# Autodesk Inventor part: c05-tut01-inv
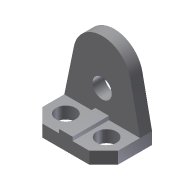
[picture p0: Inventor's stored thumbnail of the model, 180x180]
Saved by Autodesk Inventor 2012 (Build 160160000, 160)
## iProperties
Created: 2010-02
Part Number: c05-tut01-inv
Document SubType Name: Modeling
Designer: CADSoft
Density: 1 g/cm^3
Material: Default
Author: CADSoft
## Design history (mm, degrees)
sketch "Sketch1"
  geometry: L1 (-200, 0)-(0, 0); L2 (0, 0)-(0, -90); L3 (-38, -128)-(-162, -128); L4 (-200, -90)-(-200, 0); L5 (-200, -90)-(-162, -128); L6 (0, -90)-(-38, -128); C1 r 26 at (-154, -74); C2 r 26 at (-46, -74); 2 further points
  constraints: 12 end point, 2 centre point, 2 coincident, 2 equal length, 2 vertical, 1 equal radius, 1 horizontal, 1 horizontal alignment, 1 other
  dimensions: "d0" = 90 distance of L4.start L1.start; "d1" = 128 distance between parallel lines of L3 L1; "d2" = 38 horizontal distance of L4.start L3.end; "d3" = 124 distance of L3.start L3.end; "d4" = 52 diameter of C2; "d5" = 46 distance from line of L2 C2.centre; "d6" = 74 distance from line of L1 C2.centre; "d8" = 46 distance from line of L4 C1.centre
extrude "Extrusion1" new body sketch "Sketch1" distance "d9" = 32; taper "d10" = 0 deg
sketch "Sketch2"
  geometry: L1 (0, -32)-(200, -32) reference; L2 (200, -32)-(174.418, -155.424); L3 (25.582, -155.424)-(0, -32); C1 r 25.5 at (100, -96); A1 r 76 centre (100, -140) between (25.582, -155.424) and (174.418, -155.424)
  constraints: 4 end point, 2 centre point, 2 point on circle, 2 tangent, 1 equal length, 1 vertical alignment
  dimensions: "d11" = 76 radius of A1; "d12" = 108 distance from line of L1 A1.centre; "d13" = 51 diameter of C1; "d14" = 64 distance from line of L1 C1.centre
extrude "Extrusion2" join sketch "Sketch2" distance "d15" = 32; taper "d16" = 0 deg
sketch "Sketch3"
  geometry: L1 (44, 42)-(80, 42); L2 (80, 42)-(80, 32); L3 (80, 32)-(44, 32); L4 (44, 32)-(44, 42); L5 (-38, 0)-(-38, 32) reference; L6 (124, 32)-(0, 32) reference
  constraints: 8 end point, 2 horizontal, 2 vertical, 1 collinear
  dimensions: "d17" = 10 distance of L3.end L1.start; "d18" = 36 distance of L1.start L1.end; "d19" = 82 distance between parallel lines of L4 L5
extrude "Extrusion4" join sketch "Sketch3" stored distance "d22" = 10; taper "d23" = 0 deg
body "Solid1"
